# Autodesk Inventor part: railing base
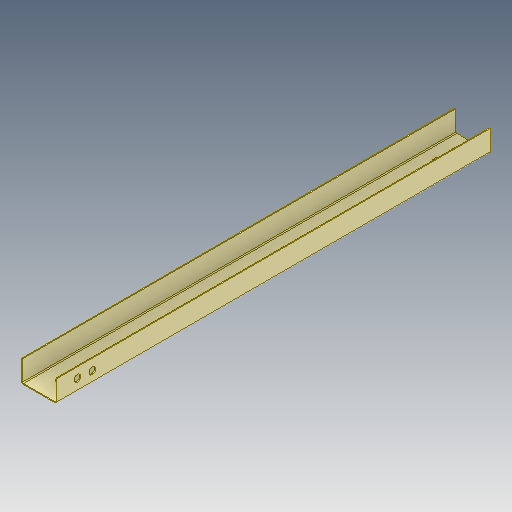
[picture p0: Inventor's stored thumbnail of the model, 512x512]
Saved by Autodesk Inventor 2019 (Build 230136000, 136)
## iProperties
Created: 2019-10
Part Number: railing base
Material: Nylon 6/6
Document SubType Name: Sheet Metal
Designer: hp
Density: 1.13 g/cm^3
Sheet Metal Rule: Default_mm
Appearance: Nylon 6
Author: hp
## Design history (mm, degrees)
node "Face1"
  sketch "Sketch1"
    geometry: L1 (288.145, 257.85)-(247.987, 257.85); L2 (247.987, 257.85)-(247.987, -236.701); L3 (247.987, -236.701)-(288.145, -236.701); L4 (288.145, -236.701)-(288.145, 257.85); 1 further point
    constraints: 8 end point, 2 parallel, 1 horizontal, 1 perpendicular
node "Flange1"
sketch "Sketch3"
  geometry: 2 further points
hole "Hole1" sketch "Sketch3" at (-268.192, 234.252) diameter "d11" = 7.9375; stored, may be unused: countersink angle "d15" = 90 deg, drill point angle "d17" = 118 deg; dims "d12" = 6, "d13" = 4, "d14" = 2, "d16" = 1 (= Thickness)
sketch "Sketch4"
  geometry: 2 further points
hole "Hole2" sketch "Sketch4" at (-268.347, 215.549) diameter "d18" = 7.9375; stored, may be unused: countersink angle "d22" = 90 deg, drill point angle "d24" = 118 deg; dims "d19" = 6, "d20" = 4, "d21" = 2, "d23" = 1 (= Thickness)
sketch "Sketch5"
  geometry: 2 further points
hole "Hole3" sketch "Sketch5" at (23.294, -11.284) diameter "d25" = 7.9375; stored, may be unused: countersink angle "d29" = 90 deg, drill point angle "d31" = 118 deg; dims "d26" = 6, "d27" = 4, "d28" = 2, "d30" = 1 (= Thickness)
sketch "Sketch6"
  geometry: 2 further points
hole "Hole4" sketch "Sketch6" at (40.348, -12.28) diameter "d32" = 7.9375; stored, may be unused: countersink angle "d36" = 90 deg, drill point angle "d38" = 118 deg; dims "d33" = 6, "d34" = 4, "d35" = 2, "d37" = 1 (= Thickness)
sketch "Sketch7"
  geometry: 2 further points
hole "Hole5" sketch "Sketch7" at (-268.294, -198.471) diameter "d39" = 12; stored, may be unused: countersink angle "d43" = 90 deg, drill point angle "d45" = 118 deg; dims "d40" = 6, "d41" = 4, "d42" = 2, "d44" = 1 (= Thickness)
sketch "Sketch8"
  geometry: 2 further points
hole "Hole6" sketch "Sketch8" at (-267.63, -219.867) diameter "d46" = 12; stored, may be unused: countersink angle "d50" = 90 deg, drill point angle "d52" = 118 deg; dims "d47" = 6, "d48" = 4, "d49" = 2, "d51" = 1 (= Thickness)
body "Solid1"
face "Plate1" dims "d0" = 1 (= Thickness)
sketch "Sketch2"
  geometry: L1 through (0, 247.275) direction (0, -1); L2 through (12.5, 0) direction (1, 0); L3 (25, 0)-(25, 494.551); L4 (25, 494.551)-(0, 494.551)
  constraints: 6 end point, 1 horizontal, 1 perpendicular, 1 vertical
face "Plate2" dims "d0" = 1 (= Thickness), "d1" = 1 (= BendReliefWidth), "d2" = 0.5 (= BendReliefDepth), "d3" = 2 (= MinimumRemnant), "d4" = 1 (= TransitionRadius), "d5" = 25, "d6" = 90 deg, "d7" = 1 (= BendRadius), "d8" = 4 (= CornerReliefSize), "d9" = 1 (= GapSize), "d10" = 1 (= JacobiRadiusSize), "SeamGap" = 0.01
bend "Bend1" dims "d0" = 1 (= Thickness), "d1" = 1 (= BendReliefWidth), "d2" = 0.5 (= BendReliefDepth), "d3" = 2 (= MinimumRemnant), "d4" = 1 (= TransitionRadius), "d5" = 25, "d6" = 90 deg, "d7" = 1 (= BendRadius), "SeamGap" = 0.01
feature "Corner1" dims "d5" = 25, "d6" = 90 deg, "d8" = 4 (= CornerReliefSize), "d9" = 1 (= GapSize), "d10" = 1 (= JacobiRadiusSize)
other parameters: "Thickness" = 1 (derived), "BendRadius" = 1 (= Thickness), "BendReliefWidth" = 1 (= Thickness), "BendReliefDepth" = 0.5 (= 0.5 x Thickness), "CornerReliefSize" = 4 (= 4 x Thickness), "MinimumRemnant" = 2 (= 2 x Thickness), "TransitionRadius" = 1 (= BendRadius), "JacobiRadiusSize" = 1 (= BendRadius), "GapSize" = 1 (= Thickness)
